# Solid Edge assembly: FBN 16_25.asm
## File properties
Title: Zylinder
Author: bmolnar
Template: iso assembly.asm
Last saved by: bmolnar
Revision: 19
Application: Solid Edge
Username: bmolnar
Dokumentum tartalom típus: 1
Document Number: FBN 16/25
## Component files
Kolbenstange.par
Profilrohr.par
Kit_1.par
Kit_2.par
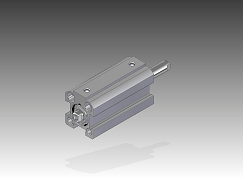
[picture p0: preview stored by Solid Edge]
